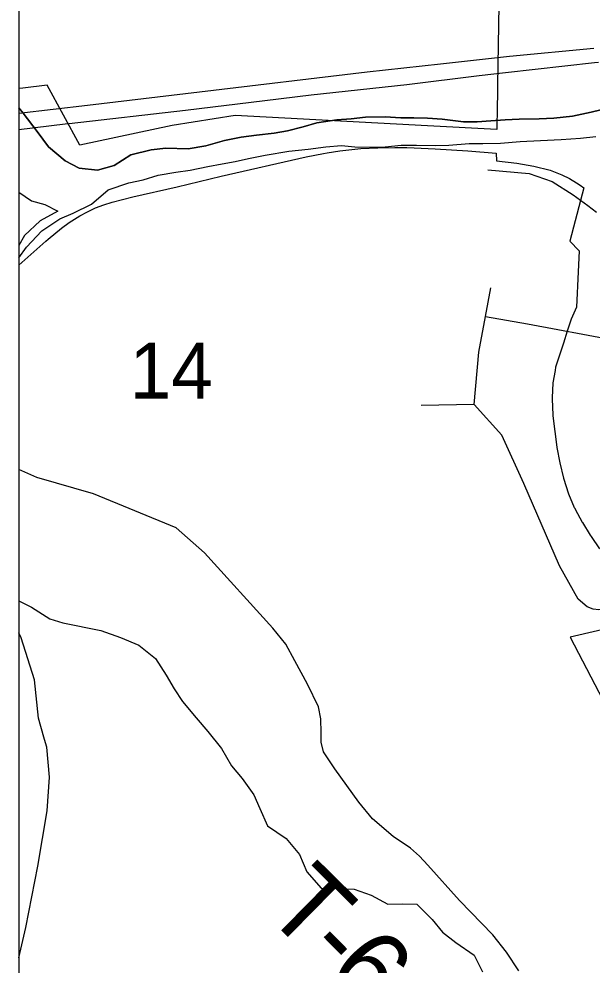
# Model space of a CAD drawing. Extents: x 39.8 to 73.8, y 13 to 35.
# Drawn here: x 41.863 to 42.292, y 31.364 to 32.071 of the extents above; entities that cross this region are included whole.
import ezdxf

# ---------------------------------------------------------------- set-up
doc = ezdxf.new("R2010")
doc.units = 0
for name, color, linetype in [('GM_X_City_Street', 7, 'Continuous'), ('GM_X_Corporation', 7, 'Continuous'), ('GM_X_County_Road', 7, 'Continuous'), ('GM_X_Major_River', 7, 'Continuous'), ('GM_X_Minor_River', 7, 'Continuous'), ('GM_X_Section_Text', 7, 'Continuous'), ('GM_X_State_Route', 7, 'Continuous'), ('GM_X_Township_Road', 7, 'Continuous'), ('GM_X_Township_Road_Text', 7, 'Continuous'), ('GM_X_US_Route', 7, 'Continuous')]:
    doc.layers.add(name, color=color, linetype=linetype)

msp = doc.modelspace()

# ---------------------------------------------------------------- linework, layer by layer
at = {"layer": 'GM_X_City_Street'}
msp.add_line((42.24311, 31.84356), (42.30725, 31.83173), dxfattribs=at)
at = {"layer": 'GM_X_Corporation'}
for points in [[(43.34809, 29.97663), (43.35246, 30.03598), (43.3561, 30.08553), (43.36111, 30.15362), (43.36109, 30.17636), (43.41195, 30.9413), (43.42785, 31.18042), (43.45938, 31.61017), (43.46036, 31.62342), (43.48793, 31.99916), (43.50044, 32.16961), (43.54165, 32.78801), (43.54199, 32.79316), (43.5449, 32.83682), (43.54599, 32.85317), (43.54652, 32.86105), (43.56813, 33.1854), (43.58174, 33.40977), (43.61576, 33.86498), (41.86298, 33.86498), (41.86298, 28.23095)], [(42.22242, 32.11205), (42.22162, 32.06679), (42.22085, 32.0223), (42.22072, 32.01507), (42.22057, 32.00639), (42.22022, 31.98876), (42.16857, 31.99152), (42.02473, 31.99921), (41.97749, 31.9918), (41.90847, 31.97712), (41.88414, 32.02194), (41.8658, 32.01979), (41.86298, 32.01946), (41.86298, 31.88753), (41.8831, 31.90535), (41.8849, 31.90695), (41.89474, 31.91504), (41.90047, 31.91933), (41.9086, 31.9244), (41.91416, 31.92741), (41.92018, 31.9302), (41.92635, 31.9326), (41.93266, 31.93462), (41.94803, 31.93847), (41.98132, 31.94608), (42.01413, 31.95402), (42.07786, 31.96847), (42.09071, 31.97096), (42.09334, 31.97147), (42.10282, 31.97293), (42.11859, 31.97459), (42.13134, 31.97528), (42.14399, 31.97531), (42.15301, 31.9753), (42.15839, 31.97505), (42.17411, 31.97443), (42.19867, 31.97302), (42.21992, 31.97106), (42.21997, 31.96534), (42.23527, 31.9637), (42.24791, 31.96148), (42.26008, 31.95837), (42.26887, 31.95497), (42.27453, 31.95223), (42.27999, 31.94912), (42.2826, 31.94722), (42.28527, 31.94527), (42.28281, 31.93576), (42.27496, 31.90542), (42.28181, 31.89829), (42.28105, 31.8825), (42.27978, 31.85603), (42.27589, 31.84718), (42.27298, 31.83817), (42.27007, 31.82916), (42.26985, 31.82849), (42.26427, 31.81123), (42.26382, 31.80866), (42.26223, 31.79956), (42.2617, 31.78838), (42.26165, 31.78726), (42.26223, 31.7755), (42.26224, 31.77521), (42.26251, 31.77282), (42.26357, 31.76327), (42.26526, 31.75144), (42.26528, 31.7513), (42.26738, 31.73974), (42.2674, 31.73965), (42.27003, 31.72837), (42.27006, 31.72825), (42.27378, 31.7167), (42.27383, 31.71653), (42.27823, 31.70638), (42.27835, 31.70609), (42.28059, 31.70191), (42.28413, 31.6953), (42.28427, 31.69504), (42.29011, 31.68558), (42.29071, 31.68461), (42.29714, 31.67549)], [(42.31922, 31.61962), (42.27501, 31.60955), (42.3121, 31.53877)]]:
    msp.add_lwpolyline(points, dxfattribs=at)
msp.add_lwpolyline([(41.86298, 32.27948), (41.86298, 31.25449), (42.42616, 31.2112), (42.505, 32.2334)], close=True, dxfattribs=at)
at = {"layer": 'GM_X_County_Road'}
for p, q in [((42.21172, 31.84901), (42.24311, 31.84356)), ((42.20324, 31.78332), (42.16379, 31.78267))]:
    msp.add_line(p, q, dxfattribs=at)
msp.add_lwpolyline([(42.31576, 31.64605), (42.30775, 31.63621), (42.3037, 31.63212), (42.30028, 31.63059), (42.2966, 31.62983), (42.29226, 31.63051), (42.28795, 31.63212), (42.28121, 31.6378), (42.26727, 31.66288), (42.24057, 31.72441), (42.22402, 31.7605), (42.20324, 31.78332), (42.2068, 31.82239), (42.21172, 31.84901), (42.21571, 31.87054)], dxfattribs=at)
at = {"layer": 'GM_X_Major_River'}
for p, q in [((41.86608, 32.00099), (41.86298, 32.00513)), ((42.30638, 32.00561), (42.29086, 32.00182)), ((41.87667, 31.98735), (41.86608, 32.00099)), ((42.1008, 31.9961), (42.08566, 31.99383)), ((42.1114, 31.99687), (42.1008, 31.9961)), ((42.12201, 31.998), (42.1114, 31.99687)), ((42.13677, 31.99838), (42.12201, 31.998)), ((42.14851, 31.99763), (42.13677, 31.99838)), ((42.15835, 31.99763), (42.14851, 31.99763)), ((42.16857, 31.99725), (42.15835, 31.99763)), ((42.17955, 31.9965), (42.16857, 31.99725)), ((42.19545, 31.9946), (42.17955, 31.9965)), ((42.2265, 31.99613), (42.2159, 31.99537)), ((42.2371, 31.99651), (42.2265, 31.99613)), ((42.25186, 31.99689), (42.2371, 31.99651)), ((42.26284, 31.99727), (42.25186, 31.99689)), ((42.27685, 31.99879), (42.26284, 31.99727)), ((42.29086, 32.00182), (42.27685, 31.99879)), ((42.07544, 31.9908), (42.0637, 31.98776)), ((42.08566, 31.99383), (42.07544, 31.9908)), ((42.20567, 31.99461), (42.19545, 31.9946)), ((42.2159, 31.99537), (42.20567, 31.99461)), ((41.885, 31.97598), (41.87667, 31.98735)), ((42.02925, 31.98321), (42.01675, 31.98055)), ((42.04061, 31.98473), (42.02925, 31.98321)), ((42.05386, 31.98624), (42.04061, 31.98473)), ((42.0637, 31.98776), (42.05386, 31.98624)), ((42.26852, 31.98135), (42.2829, 31.98249)), ((42.2829, 31.98249), (42.29426, 31.98363)), ((41.89749, 31.96537), (41.885, 31.97598)), ((41.97283, 31.97486), (41.96185, 31.97372)), ((41.98949, 31.97449), (41.97283, 31.97486)), ((42.00274, 31.97676), (41.98949, 31.97449)), ((42.01675, 31.98055), (42.00274, 31.97676)), ((42.07922, 31.97412), (42.09247, 31.97602)), ((42.09247, 31.97602), (42.10421, 31.97678)), ((42.10421, 31.97678), (42.11405, 31.97602)), ((42.11405, 31.97602), (42.12579, 31.97564)), ((42.12579, 31.97564), (42.13677, 31.97602)), ((42.13677, 31.97602), (42.14888, 31.97716)), ((42.14888, 31.97716), (42.16024, 31.97717)), ((42.16024, 31.97717), (42.17425, 31.97679)), ((42.17425, 31.97679), (42.18447, 31.97717)), ((42.18447, 31.97717), (42.19961, 31.97831)), ((42.19961, 31.97831), (42.20983, 31.97831)), ((42.20983, 31.97831), (42.22308, 31.97869)), ((42.22308, 31.97869), (42.23785, 31.97983)), ((42.23785, 31.97983), (42.25299, 31.98059)), ((42.25299, 31.98059), (42.26852, 31.98135)), ((41.94671, 31.96993), (41.93422, 31.96197)), ((41.96185, 31.97372), (41.94671, 31.96993)), ((42.03454, 31.96729), (42.04704, 31.96957)), ((42.04704, 31.96957), (42.06483, 31.9726)), ((42.06483, 31.9726), (42.07922, 31.97412)), ((41.90809, 31.96007), (41.89749, 31.96537)), ((41.93422, 31.96197), (41.92172, 31.95856)), ((41.991, 31.95857), (42.00425, 31.96122)), ((42.00425, 31.96122), (42.01486, 31.96312)), ((42.01486, 31.96312), (42.0247, 31.96502)), ((42.0247, 31.96502), (42.03454, 31.96729)), ((41.92172, 31.95856), (41.90809, 31.96007)), ((41.95579, 31.95136), (41.96715, 31.95477)), ((41.96715, 31.95477), (41.9804, 31.95705)), ((41.9804, 31.95705), (41.991, 31.95857)), ((41.92967, 31.94378), (41.94519, 31.94909)), ((41.94519, 31.94909), (41.95579, 31.95136)), ((41.86298, 31.9421), (41.8725, 31.93543)), ((41.91717, 31.93316), (41.92967, 31.94378)), ((41.8725, 31.93543), (41.88234, 31.93278)), ((41.88234, 31.93278), (41.89218, 31.92785)), ((41.90354, 31.92634), (41.91717, 31.93316)), ((41.89218, 31.92785), (41.87893, 31.92065)), ((41.89369, 31.92217), (41.90354, 31.92634)), ((41.87893, 31.92065), (41.86719, 31.90966)), ((41.88006, 31.91307), (41.89369, 31.92217)), ((41.8687, 31.90094), (41.88006, 31.91307)), ((41.86719, 31.90966), (41.86298, 31.90213)), ((41.86298, 31.89297), (41.8687, 31.90094))]:
    msp.add_line(p, q, dxfattribs=at)
for points in [[(41.86298, 32.00513), (41.86608, 32.00099), (41.87667, 31.98735), (41.885, 31.97598), (41.89749, 31.96537), (41.90809, 31.96007), (41.92172, 31.95856), (41.93422, 31.96197), (41.94671, 31.96993), (41.96185, 31.97372), (41.97283, 31.97486), (41.98949, 31.97449), (42.00274, 31.97676), (42.01675, 31.98055), (42.02925, 31.98321), (42.04061, 31.98473), (42.05386, 31.98624), (42.0637, 31.98776), (42.07544, 31.9908), (42.08566, 31.99383), (42.1008, 31.9961), (42.1114, 31.99687), (42.12201, 31.998), (42.13677, 31.99838), (42.14851, 31.99763), (42.15835, 31.99763), (42.16857, 31.99725), (42.17955, 31.9965), (42.19545, 31.9946), (42.20567, 31.99461), (42.2159, 31.99537), (42.2265, 31.99613), (42.2371, 31.99651), (42.25186, 31.99689), (42.26284, 31.99727), (42.27685, 31.99879), (42.29086, 32.00182), (42.30638, 32.00561)], [(41.86298, 31.89297), (41.8687, 31.90094), (41.88006, 31.91307), (41.89369, 31.92217), (41.90354, 31.92634), (41.91717, 31.93316), (41.92967, 31.94378), (41.94519, 31.94909), (41.95579, 31.95136), (41.96715, 31.95477), (41.9804, 31.95705), (41.991, 31.95857), (42.00425, 31.96122), (42.01486, 31.96312), (42.0247, 31.96502), (42.03454, 31.96729), (42.04704, 31.96957), (42.06483, 31.9726), (42.07922, 31.97412), (42.09247, 31.97602), (42.10421, 31.97678), (42.11405, 31.97602), (42.12579, 31.97564), (42.13677, 31.97602), (42.14888, 31.97716), (42.16024, 31.97717), (42.17425, 31.97679), (42.18447, 31.97717), (42.19961, 31.97831), (42.20983, 31.97831), (42.22308, 31.97869), (42.23785, 31.97983), (42.25299, 31.98059), (42.26852, 31.98135), (42.2829, 31.98249), (42.29426, 31.98363)], [(41.86298, 31.9421), (41.8725, 31.93543), (41.88234, 31.93278), (41.89218, 31.92785), (41.87893, 31.92065), (41.86719, 31.90966), (41.86298, 31.90213)]]:
    msp.add_lwpolyline(points, dxfattribs=at)
at = {"layer": 'GM_X_Minor_River'}
msp.add_lwpolyline([(41.86298, 31.63658), (41.87242, 31.63186), (41.88605, 31.62314), (41.89589, 31.62011), (41.92429, 31.61443), (41.93905, 31.60913), (41.95268, 31.60345), (41.96517, 31.59359), (41.97312, 31.58109), (41.97917, 31.57086), (41.98523, 31.56138), (41.99545, 31.54926), (42.00415, 31.53903), (42.01437, 31.52614), (42.02194, 31.51326), (42.02989, 31.50378), (42.03859, 31.49166), (42.04313, 31.48142), (42.04881, 31.46854), (42.06281, 31.45907), (42.07265, 31.44694), (42.07833, 31.43406), (42.08893, 31.42193), (42.10066, 31.42156), (42.11354, 31.42118), (42.12641, 31.41663), (42.1389, 31.40981), (42.14988, 31.41019), (42.16048, 31.40981), (42.17183, 31.39845), (42.17978, 31.38897), (42.18962, 31.38139), (42.20325, 31.37192), (42.20968, 31.35942)], dxfattribs=at)
at = {"layer": 'GM_X_State_Route'}
for points in [[(42.21361, 31.95863), (42.24459, 31.95589), (42.26161, 31.95007), (42.27747, 31.94008), (42.28826, 31.93211), (42.2949, 31.9272)], [(41.88162, 31.53472), (41.87752, 31.54886), (41.87454, 31.57754), (41.86461, 31.60901), (41.86298, 31.61264)], [(41.86298, 31.36976), (41.86803, 31.39259), (41.87709, 31.43844), (41.88422, 31.47975), (41.88592, 31.50478), (41.88381, 31.52719), (41.88353, 31.52812), (41.88162, 31.53472)]]:
    msp.add_lwpolyline(points, dxfattribs=at)
at = {"layer": 'GM_X_Township_Road'}
msp.add_lwpolyline([(42.23665, 31.36007), (42.22759, 31.37394), (42.21724, 31.38707), (42.19246, 31.41258), (42.16861, 31.43902), (42.16251, 31.44568), (42.15567, 31.45178), (42.14291, 31.46047), (42.12738, 31.47378), (42.11703, 31.48617), (42.09928, 31.51113), (42.09059, 31.52389), (42.08892, 31.53092), (42.08892, 31.53794), (42.08874, 31.54848), (42.08707, 31.55736), (42.07875, 31.57437), (42.06932, 31.59175), (42.06246, 31.60415), (42.05288, 31.61627), (42.00185, 31.67237), (41.98043, 31.69126), (41.91869, 31.71663), (41.8764, 31.72875), (41.86298, 31.73467)], dxfattribs=at)
at = {"layer": 'GM_X_US_Route'}
msp.add_line((41.86298, 31.98891), (41.8976, 31.99297), dxfattribs=at)
for points in [[(41.86298, 32.00109), (41.91437, 32.00709), (41.9981, 32.01696), (42.12345, 32.03192), (42.17806, 32.03801), (42.22988, 32.04377), (42.29279, 32.04953)], [(42.22687, 32.03145), (42.29325, 32.03905), (42.29634, 32.03928)], [(42.04688, 32.01046), (42.08154, 32.0147), (42.15294, 32.0226), (42.20706, 32.02918), (42.22687, 32.03145)], [(41.8976, 31.99297), (41.9006, 31.99332), (41.98745, 32.00319), (42.04688, 32.01046)]]:
    msp.add_lwpolyline(points, dxfattribs=at)

# ---------------------------------------------------------------- texts
at = {"layer": 'GM_X_Section_Text'}
msp.add_text('14', height=0.041856, rotation=0.00001, dxfattribs=at).set_placement((41.94571, 31.78779))
at = {"layer": 'GM_X_Township_Road_Text'}
for s, rotation, p in [('T', 315.45758, (42.04501, 31.40408)), ('-', 314.58598, (42.07514, 31.37443)), ('6', 313.50593, (42.09132, 31.35802))]:
    msp.add_text(s, height=0.05682, rotation=rotation, dxfattribs=at).set_placement(p)

doc.saveas('drawing.dxf')
